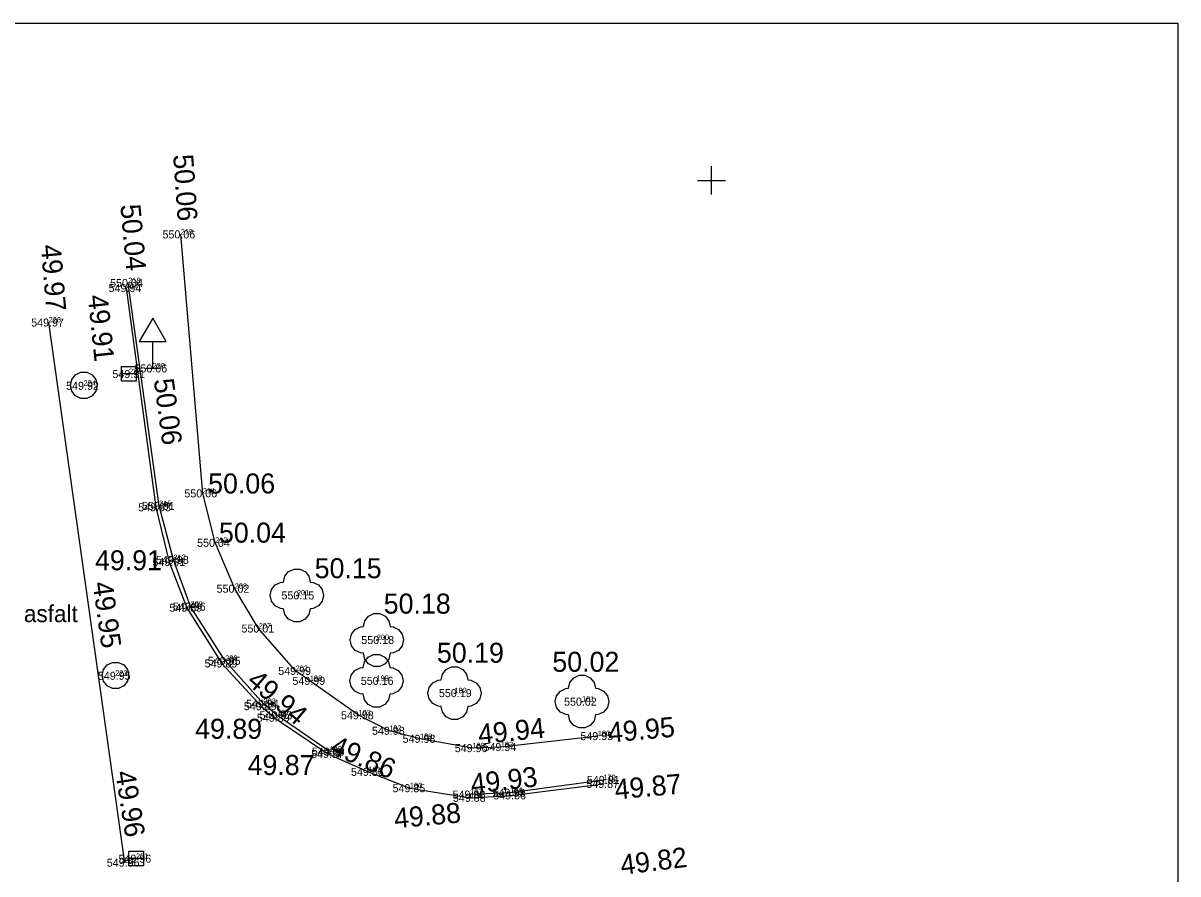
# Model space of a CAD drawing. Extents: x -866693 to -866303, y -1041966 to -1040244.
# Drawn here: x -866525.8 to -866482.52, y -1040275.97 to -1040244.11 of the extents above; entities that cross this region are included whole.
import ezdxf

# ---------------------------------------------------------------- set-up
doc = ezdxf.new("R2010")
doc.units = 0
for name, color, linetype in [('1 hrana zpevněné komunikace-plocha', 7, 'Continuous'), ('3 osa komunikace', 7, 'Continuous'), ('42 dopravní značka', 7, 'Continuous'), ('5 obrubník nahoře (chodník)', 7, 'Continuous'), ('52 šachta bez rozlišení', 7, 'Continuous'), ('55 uliční vpust', 7, 'Continuous'), ('60 strom bez rozlišení', 7, 'Continuous'), ('Bod', 7, 'Continuous'), ('Formát', 7, 'Continuous'), ('Nadmořská výška', 7, 'Continuous'), ('Nadmořská výška_tisk', 7, 'Continuous'), ('popisy', 7, 'Continuous'), ('Síť křížek', 7, 'Continuous'), ('Číslo bodu', 7, 'Continuous')]:
    doc.layers.add(name, color=color, linetype=linetype)

msp = doc.modelspace()

# ---------------------------------------------------------------- linework, layer by layer
at = {"layer": '1 hrana zpevněné komunikace-plocha'}
for points in [[(-866504.259, -1040270.807), (-866507.893, -1040271.221), (-866508.96, -1040271.262), (-866510.92, -1040270.914), (-866512.074, -1040270.609), (-866513.229, -1040270.028), (-866515.049, -1040268.741), (-866515.584, -1040268.366), (-866516.969, -1040266.779), (-866517.866, -1040265.292), (-866518.597, -1040263.565), (-866519.065, -1040261.723), (-866519.89, -1040252.024)], [(-866521.939, -1040254.026), (-866520.825, -1040262.235), (-866520.325, -1040264.291), (-866519.661, -1040266.004), (-866518.344, -1040268.088), (-866516.869, -1040269.686), (-866516.381, -1040270.121), (-866514.354, -1040271.482), (-866512.852, -1040272.151), (-866511.3, -1040272.758), (-866509.036, -1040273.121), (-866507.518, -1040273.034), (-866504.041, -1040272.602)]]:
    msp.add_lwpolyline(points, dxfattribs=at)
at = {"layer": '3 osa komunikace'}
msp.add_line((-866524.841, -1040255.315), (-866522.001, -1040275.551), dxfattribs=at)
at = {"layer": '42 dopravní značka'}
for points in [[(-866520.94, -1040257.035), (-866520.94, -1040256.035), (-866520.44, -1040256.035), (-866520.94, -1040255.16), (-866521.44, -1040256.035), (-866520.94, -1040256.035)], [(-866521.19, -1040257.035), (-866520.69, -1040257.035)]]:
    msp.add_lwpolyline(points, dxfattribs=at)
at = {"layer": '5 obrubník nahoře (chodník)'}
for points in [[(-866514.354, -1040271.482), (-866514.316, -1040271.392), (-866516.283, -1040270.026), (-866516.785, -1040269.6), (-866518.223, -1040267.986), (-866519.522, -1040265.959), (-866520.161, -1040264.21), (-866520.698, -1040262.189), (-866521.856, -1040253.842)], [(-866504.048, -1040272.454), (-866507.549, -1040272.93), (-866509.049, -1040272.998), (-866509.036, -1040273.121)]]:
    msp.add_lwpolyline(points, dxfattribs=at)
at = {"layer": '52 šachta bez rozlišení'}
for p, q in [((-866524.016, -1040257.674), (-866523.966, -1040257.457)), ((-866523.966, -1040257.457), (-866523.828, -1040257.283)), ((-866523.828, -1040257.283), (-866523.627, -1040257.186)), ((-866523.627, -1040257.186), (-866523.404, -1040257.186)), ((-866523.404, -1040257.186), (-866523.204, -1040257.283)), ((-866523.204, -1040257.283), (-866523.065, -1040257.457)), ((-866523.065, -1040257.457), (-866523.016, -1040257.674)), ((-866523.966, -1040257.891), (-866524.016, -1040257.674)), ((-866523.828, -1040258.065), (-866523.966, -1040257.891)), ((-866523.065, -1040257.891), (-866523.204, -1040258.065)), ((-866523.016, -1040257.674), (-866523.065, -1040257.891)), ((-866523.627, -1040258.161), (-866523.828, -1040258.065)), ((-866523.404, -1040258.161), (-866523.627, -1040258.161)), ((-866523.204, -1040258.065), (-866523.404, -1040258.161)), ((-866522.778, -1040268.318), (-866522.64, -1040268.144)), ((-866522.64, -1040268.144), (-866522.439, -1040268.047)), ((-866522.439, -1040268.047), (-866522.216, -1040268.047)), ((-866522.216, -1040268.047), (-866522.016, -1040268.144)), ((-866522.016, -1040268.144), (-866521.877, -1040268.318)), ((-866522.828, -1040268.535), (-866522.778, -1040268.318)), ((-866522.778, -1040268.752), (-866522.828, -1040268.535)), ((-866521.877, -1040268.318), (-866521.828, -1040268.535)), ((-866521.828, -1040268.535), (-866521.877, -1040268.752)), ((-866522.64, -1040268.926), (-866522.778, -1040268.752)), ((-866522.439, -1040269.022), (-866522.64, -1040268.926)), ((-866522.216, -1040269.022), (-866522.439, -1040269.022)), ((-866522.016, -1040268.926), (-866522.216, -1040269.022)), ((-866521.877, -1040268.752), (-866522.016, -1040268.926))]:
    msp.add_line(p, q, dxfattribs=at)
at = {"layer": '55 uliční vpust'}
for points in [[(-866521.553, -1040257.245), (-866521.553, -1040257.52), (-866522.103, -1040257.52), (-866522.103, -1040256.97), (-866521.553, -1040256.97), (-866521.553, -1040257.245), (-866522.103, -1040257.245)], [(-866521.286, -1040275.399), (-866521.286, -1040275.674), (-866521.836, -1040275.674), (-866521.836, -1040275.124), (-866521.286, -1040275.124), (-866521.286, -1040275.399), (-866521.836, -1040275.399)]]:
    msp.add_lwpolyline(points, dxfattribs=at)
at = {"layer": '60 strom bez rozlišení'}
for points in [[(-866514.533, -1040265.539), (-866514.583, -1040265.756), (-866514.721, -1040265.93), (-866514.922, -1040266.027), (-866515.033, -1040266.039), (-866515.083, -1040266.256), (-866515.221, -1040266.43), (-866515.422, -1040266.527), (-866515.644, -1040266.527), (-866515.845, -1040266.43), (-866515.983, -1040266.256), (-866516.033, -1040266.039), (-866516.144, -1040266.027), (-866516.345, -1040265.93), (-866516.483, -1040265.756), (-866516.533, -1040265.539), (-866516.483, -1040265.322), (-866516.345, -1040265.148), (-866516.144, -1040265.052), (-866516.033, -1040265.039), (-866515.983, -1040264.822), (-866515.845, -1040264.648), (-866515.644, -1040264.552), (-866515.422, -1040264.552), (-866515.221, -1040264.648), (-866515.083, -1040264.822), (-866515.033, -1040265.039), (-866514.922, -1040265.052), (-866514.721, -1040265.148), (-866514.583, -1040265.322)], [(-866511.542, -1040267.209), (-866511.591, -1040267.426), (-866511.731, -1040267.6), (-866511.931, -1040267.697), (-866512.042, -1040267.709), (-866512.091, -1040267.926), (-866512.231, -1040268.1), (-866512.431, -1040268.197), (-866512.653, -1040268.197), (-866512.853, -1040268.1), (-866512.993, -1040267.926), (-866513.042, -1040267.709), (-866513.153, -1040267.697), (-866513.353, -1040267.6), (-866513.493, -1040267.426), (-866513.542, -1040267.209), (-866513.493, -1040266.992), (-866513.353, -1040266.818), (-866513.153, -1040266.721), (-866513.042, -1040266.709), (-866512.993, -1040266.492), (-866512.853, -1040266.318), (-866512.653, -1040266.221), (-866512.431, -1040266.221), (-866512.231, -1040266.318), (-866512.091, -1040266.492), (-866512.042, -1040266.709), (-866511.931, -1040266.721), (-866511.731, -1040266.818), (-866511.591, -1040266.992)], [(-866511.552, -1040268.739), (-866511.601, -1040268.956), (-866511.741, -1040269.13), (-866511.941, -1040269.226), (-866512.052, -1040269.239), (-866512.101, -1040269.456), (-866512.241, -1040269.63), (-866512.441, -1040269.726), (-866512.663, -1040269.726), (-866512.863, -1040269.63), (-866513.003, -1040269.456), (-866513.052, -1040269.239), (-866513.163, -1040269.226), (-866513.363, -1040269.13), (-866513.503, -1040268.956), (-866513.552, -1040268.739), (-866513.503, -1040268.522), (-866513.363, -1040268.348), (-866513.163, -1040268.252), (-866513.052, -1040268.239), (-866513.003, -1040268.022), (-866512.863, -1040267.848), (-866512.663, -1040267.752), (-866512.441, -1040267.752), (-866512.241, -1040267.848), (-866512.101, -1040268.022), (-866512.052, -1040268.239), (-866511.941, -1040268.252), (-866511.741, -1040268.348), (-866511.601, -1040268.522)], [(-866508.633, -1040269.201), (-866508.682, -1040269.418), (-866508.821, -1040269.592), (-866509.022, -1040269.689), (-866509.133, -1040269.701), (-866509.182, -1040269.918), (-866509.321, -1040270.092), (-866509.522, -1040270.189), (-866509.744, -1040270.189), (-866509.944, -1040270.092), (-866510.084, -1040269.918), (-866510.133, -1040269.701), (-866510.244, -1040269.689), (-866510.444, -1040269.592), (-866510.584, -1040269.418), (-866510.633, -1040269.201), (-866510.584, -1040268.984), (-866510.444, -1040268.81), (-866510.244, -1040268.714), (-866510.133, -1040268.701), (-866510.084, -1040268.484), (-866509.944, -1040268.31), (-866509.744, -1040268.214), (-866509.522, -1040268.214), (-866509.321, -1040268.31), (-866509.182, -1040268.484), (-866509.133, -1040268.701), (-866509.022, -1040268.714), (-866508.821, -1040268.81), (-866508.682, -1040268.984)], [(-866503.852, -1040269.517), (-866503.902, -1040269.734), (-866504.041, -1040269.908), (-866504.241, -1040270.005), (-866504.352, -1040270.017), (-866504.402, -1040270.234), (-866504.541, -1040270.408), (-866504.741, -1040270.505), (-866504.963, -1040270.505), (-866505.164, -1040270.408), (-866505.302, -1040270.234), (-866505.352, -1040270.017), (-866505.463, -1040270.005), (-866505.664, -1040269.908), (-866505.802, -1040269.734), (-866505.852, -1040269.517), (-866505.802, -1040269.3), (-866505.664, -1040269.126), (-866505.463, -1040269.03), (-866505.352, -1040269.017), (-866505.302, -1040268.8), (-866505.164, -1040268.626), (-866504.963, -1040268.53), (-866504.741, -1040268.53), (-866504.541, -1040268.626), (-866504.402, -1040268.8), (-866504.352, -1040269.017), (-866504.241, -1040269.03), (-866504.041, -1040269.126), (-866503.902, -1040269.3)]]:
    msp.add_lwpolyline(points, close=True, dxfattribs=at)
for points in [[(-866515.558, -1040265.539), (-866515.533, -1040265.539), (-866515.508, -1040265.539)], [(-866512.567, -1040267.209), (-866512.542, -1040267.209), (-866512.517, -1040267.209)], [(-866512.577, -1040268.739), (-866512.552, -1040268.739), (-866512.527, -1040268.739)], [(-866509.658, -1040269.201), (-866509.633, -1040269.201), (-866509.608, -1040269.201)], [(-866504.877, -1040269.517), (-866504.852, -1040269.517), (-866504.827, -1040269.517)]]:
    msp.add_lwpolyline(points, dxfattribs=at)
at = {"layer": 'Bod'}
for p, q in [((-866519.89, -1040252.024), (-866519.89, -1040252.024)), ((-866521.939, -1040254.026), (-866521.939, -1040254.026)), ((-866521.856, -1040253.842), (-866521.856, -1040253.842)), ((-866524.841, -1040255.315), (-866524.841, -1040255.315)), ((-866520.94, -1040257.035), (-866520.94, -1040257.035)), ((-866521.828, -1040257.245), (-866521.828, -1040257.245)), ((-866523.531, -1040257.686), (-866523.531, -1040257.686)), ((-866519.065, -1040261.723), (-866519.065, -1040261.723)), ((-866520.825, -1040262.235), (-866520.825, -1040262.235)), ((-866520.698, -1040262.189), (-866520.698, -1040262.189)), ((-866518.597, -1040263.565), (-866518.597, -1040263.565)), ((-866520.325, -1040264.291), (-866520.325, -1040264.291)), ((-866520.161, -1040264.21), (-866520.161, -1040264.21)), ((-866517.866, -1040265.292), (-866517.866, -1040265.292)), ((-866515.533, -1040265.539), (-866515.533, -1040265.539)), ((-866519.661, -1040266.004), (-866519.661, -1040266.004)), ((-866519.522, -1040265.959), (-866519.522, -1040265.959)), ((-866516.969, -1040266.779), (-866516.969, -1040266.779)), ((-866512.542, -1040267.209), (-866512.542, -1040267.209)), ((-866518.344, -1040268.088), (-866518.344, -1040268.088)), ((-866518.223, -1040267.986), (-866518.223, -1040267.986)), ((-866522.343, -1040268.547), (-866522.343, -1040268.547)), ((-866515.584, -1040268.366), (-866515.584, -1040268.366)), ((-866515.049, -1040268.741), (-866515.049, -1040268.741)), ((-866512.552, -1040268.739), (-866512.552, -1040268.739)), ((-866516.785, -1040269.6), (-866516.785, -1040269.6)), ((-866509.633, -1040269.201), (-866509.633, -1040269.201)), ((-866504.852, -1040269.517), (-866504.852, -1040269.517)), ((-866516.869, -1040269.686), (-866516.869, -1040269.686)), ((-866516.283, -1040270.026), (-866516.283, -1040270.026)), ((-866513.229, -1040270.028), (-866513.229, -1040270.028)), ((-866516.381, -1040270.121), (-866516.381, -1040270.121)), ((-866512.074, -1040270.609), (-866512.074, -1040270.609)), ((-866504.259, -1040270.807), (-866504.259, -1040270.807)), ((-866510.92, -1040270.914), (-866510.92, -1040270.914)), ((-866508.96, -1040271.262), (-866508.96, -1040271.262)), ((-866507.893, -1040271.221), (-866507.893, -1040271.221)), ((-866514.354, -1040271.482), (-866514.354, -1040271.482)), ((-866514.316, -1040271.392), (-866514.316, -1040271.392)), ((-866512.852, -1040272.151), (-866512.852, -1040272.151)), ((-866504.048, -1040272.454), (-866504.048, -1040272.454)), ((-866504.041, -1040272.602), (-866504.041, -1040272.602)), ((-866511.3, -1040272.758), (-866511.3, -1040272.758)), ((-866509.049, -1040272.998), (-866509.049, -1040272.998)), ((-866507.549, -1040272.93), (-866507.549, -1040272.93)), ((-866507.518, -1040273.034), (-866507.518, -1040273.034)), ((-866509.036, -1040273.121), (-866509.036, -1040273.121)), ((-866522.001, -1040275.551), (-866522.001, -1040275.551)), ((-866521.561, -1040275.399), (-866521.561, -1040275.399))]:
    msp.add_line(p, q, dxfattribs=at)
at = {"layer": 'Formát'}
msp.add_lwpolyline([(-866692.523, -1040244.107), (-866482.523, -1040244.107), (-866482.523, -1040541.107), (-866692.523, -1040541.107)], close=True, dxfattribs=at)
at = {"layer": 'Síť křížek'}
for p, q in [((-866500, -1040250.53), (-866500, -1040249.47)), ((-866500.53, -1040250), (-866499.47, -1040250))]:
    msp.add_line(p, q, dxfattribs=at)

# ---------------------------------------------------------------- texts
at = {"layer": 'Nadmořská výška'}
for s, p in [('550.06', (-866520.572, -1040252.17)), ('549.94', (-866522.593, -1040254.18)), ('550.04', (-866522.535, -1040253.99)), ('549.97', (-866525.493, -1040255.47)), ('550.06', (-866521.622, -1040257.19)), ('549.91', (-866522.449, -1040257.4)), ('549.92', (-866524.183, -1040257.84)), ('550.06', (-866519.752, -1040261.87)), ('549.93', (-866521.483, -1040262.39)), ('550.01', (-866521.342, -1040262.34)), ('550.04', (-866519.275, -1040263.72)), ('549.91', (-866520.949, -1040264.44)), ('549.98', (-866520.813, -1040264.36)), ('550.02', (-866518.545, -1040265.44)), ('550.15', (-866516.113, -1040265.69)), ('549.89', (-866520.313, -1040266.15)), ('549.96', (-866520.18, -1040266.11)), ('550.01', (-866517.612, -1040266.93)), ('550.18', (-866513.123, -1040267.36)), ('549.95', (-866518.873, -1040268.14)), ('549.89', (-866518.993, -1040268.24)), ('549.99', (-866516.234, -1040268.52)), ('549.95', (-866522.993, -1040268.7)), ('549.99', (-866515.704, -1040268.89)), ('550.16', (-866513.141, -1040268.89)), ('550.19', (-866510.214, -1040269.35)), ('549.89', (-866517.523, -1040269.84)), ('549.94', (-866517.443, -1040269.75)), ('550.02', (-866505.525, -1040269.67)), ('549.89', (-866517.033, -1040270.27)), ('549.93', (-866516.933, -1040270.18)), ('549.98', (-866513.883, -1040270.18)), ('549.98', (-866512.723, -1040270.76)), ('549.98', (-866511.573, -1040271.06)), ('549.95', (-866504.913, -1040270.96)), ('549.87', (-866515.001, -1040271.63)), ('549.89', (-866514.973, -1040271.54)), ('549.96', (-866509.62, -1040271.41)), ('549.94', (-866508.543, -1040271.37)), ('549.86', (-866513.509, -1040272.3)), ('549.85', (-866511.951, -1040272.91)), ('549.87', (-866504.691, -1040272.75)), ('549.91', (-866504.669, -1040272.6)), ('549.88', (-866509.701, -1040273.15)), ('549.88', (-866509.691, -1040273.27)), ('549.93', (-866508.203, -1040273.08)), ('549.86', (-866508.179, -1040273.18)), ('549.96', (-866522.66, -1040275.7)), ('549.96', (-866522.22, -1040275.55))]:
    msp.add_text(s, height=0.3, dxfattribs=at).set_placement(p)
at = {"layer": 'Nadmořská výška_tisk'}
for s, rotation, p in [('50.06', 273.9755, (-866520.173, -1040249.044)), ('50.04', 275.2014, (-866522.151, -1040250.919)), ('49.97', 274.8075, (-866525.133, -1040252.428)), ('49.91', 275.8648, (-866523.372, -1040254.316)), ('50.06', 277.6247, (-866520.901, -1040257.461)), ('49.95', 277.8557, (-866523.191, -1040265.07)), ('49.94', 319.5405, (-866517.456, -1040268.825)), ('49.94', 5.8394, (-866508.708, -1040271.116)), ('49.95', 5.0874, (-866503.846, -1040271.051)), ('49.86', 336.88, (-866514.348, -1040271.447)), ('49.96', 278.9308, (-866522.345, -1040272.157)), ('49.93', 6.576, (-866508.98, -1040272.974)), ('49.87', 5.0304, (-866503.599, -1040273.181)), ('49.88', 5.1749, (-866511.86, -1040274.265)), ('49.82', 6.9232, (-866503.369, -1040276.007))]:
    msp.add_text(s, height=0.75, rotation=rotation, dxfattribs=at).set_placement(p)
for s, p in [('50.06', (-866518.861, -1040261.723)), ('50.04', (-866518.457, -1040263.565)), ('49.91', (-866523.101, -1040264.599)), ('50.15', (-866514.869, -1040264.897)), ('50.18', (-866512.282, -1040266.223)), ('50.19', (-866510.289, -1040268.062)), ('50.02', (-866505.963, -1040268.401)), ('49.89', (-866519.349, -1040270.91)), ('49.87', (-866517.383, -1040272.267))]:
    msp.add_text(s, height=0.75, dxfattribs=at).set_placement(p)
at = {"layer": 'popisy'}
msp.add_text('asfalt', height=0.632, dxfattribs=at).set_placement((-866525.766, -1040266.541))
at = {"layer": 'Číslo bodu'}
for s, p in [('219', (-866519.89, -1040252.024)), ('217', (-866521.939, -1040254.026)), ('218', (-866521.856, -1040253.842)), ('226', (-866524.841, -1040255.315)), ('225', (-866521.828, -1040257.245)), ('220', (-866520.94, -1040257.035)), ('224', (-866523.531, -1040257.686)), ('214', (-866519.065, -1040261.723)), ('216', (-866520.825, -1040262.235)), ('215', (-866520.698, -1040262.189)), ('213', (-866518.597, -1040263.565)), ('211', (-866520.325, -1040264.291)), ('212', (-866520.161, -1040264.21)), ('208', (-866517.866, -1040265.292)), ('201', (-866515.533, -1040265.539)), ('210', (-866519.661, -1040266.004)), ('209', (-866519.522, -1040265.959)), ('207', (-866516.969, -1040266.779)), ('200', (-866512.542, -1040267.209)), ('206', (-866518.223, -1040267.986)), ('205', (-866518.344, -1040268.088)), ('202', (-866515.584, -1040268.366)), ('223', (-866522.343, -1040268.547)), ('198', (-866515.049, -1040268.741)), ('199', (-866512.552, -1040268.739)), ('182', (-866509.633, -1040269.201)), ('204', (-866516.869, -1040269.686)), ('203', (-866516.785, -1040269.6)), ('181', (-866504.852, -1040269.517)), ('196', (-866516.381, -1040270.121)), ('197', (-866516.283, -1040270.026)), ('193', (-866513.229, -1040270.028)), ('192', (-866512.074, -1040270.609)), ('189', (-866510.92, -1040270.914)), ('180', (-866504.259, -1040270.807)), ('194', (-866514.354, -1040271.482)), ('195', (-866514.316, -1040271.392)), ('188', (-866508.96, -1040271.262)), ('183', (-866507.893, -1040271.221)), ('191', (-866512.852, -1040272.151)), ('190', (-866511.3, -1040272.758)), ('179', (-866504.048, -1040272.454)), ('178', (-866504.041, -1040272.602)), ('187', (-866509.049, -1040272.998)), ('186', (-866509.036, -1040273.121)), ('184', (-866507.549, -1040272.93)), ('185', (-866507.518, -1040273.034)), ('221', (-866521.561, -1040275.399)), ('222', (-866522.001, -1040275.551))]:
    msp.add_text(s, height=0.2, dxfattribs=at).set_placement(p)

doc.saveas('drawing.dxf')
